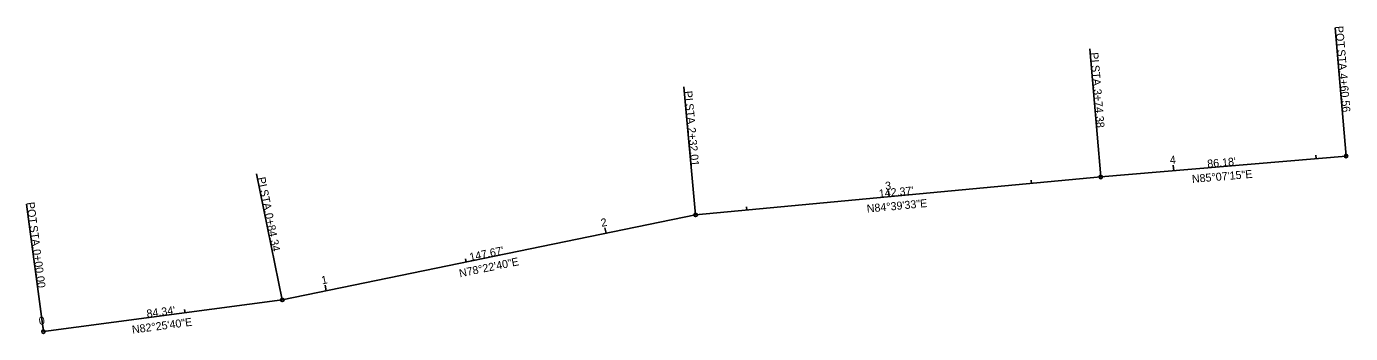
# Model space of a CAD drawing. Extents: x 227242 to 227706, y 293934 to 294041.
import ezdxf

# ---------------------------------------------------------------- set-up
doc = ezdxf.new("R2010")
doc.units = 0
for name, color, linetype in [('GE_P_Alignment', 7, 'Continuous'), ('GE_P_Alignment_100_Bearings', 7, 'Continuous'), ('GE_P_Alignment_100_Cardinal_Points', 7, 'Continuous'), ('GE_P_Alignment_100_Curve_Data', 7, 'Continuous'), ('SC_Scratch1', 7, 'Continuous'), ('SC_Scratch2', 7, 'Continuous')]:
    doc.layers.add(name, color=color, linetype=linetype)

msp = doc.modelspace()

# ---------------------------------------------------------------- linework, layer by layer
at = {"layer": 'GE_P_Alignment'}
for p, q in [((227618.14, 293988.75), (227704.01, 293996.08)), ((227476.38, 293975.49), (227618.14, 293988.75)), ((227331.74, 293945.74), (227476.38, 293975.49)), ((227248.14, 293934.63), (227331.74, 293945.74))]:
    msp.add_line(p, q, dxfattribs=at)
at = {"layer": 'GE_P_Alignment_100_Bearings'}
for p, q in [((227704.01, 293996.08), (227700.18, 294040.91)), ((227618.14, 293988.75), (227614.31, 294033.58)), ((227476.38, 293975.49), (227472.2, 294020.3)), ((227331.74, 293945.74), (227322.68, 293989.82)), ((227248.14, 293934.63), (227242.21, 293979.24))]:
    msp.add_line(p, q, dxfattribs=at)
for centre in [(227704.01, 293996.08), (227618.14, 293988.75), (227476.38, 293975.49), (227331.74, 293945.74), (227248.14, 293934.63)]:
    msp.add_circle(centre, 0.6, dxfattribs=at)
at = {"layer": 'GE_P_Alignment_100_Curve_Data'}
for p, q in [((227693.49, 293995.18), (227693.38, 293996.37)), ((227643.67, 293990.93), (227643.5, 293992.92)), ((227593.87, 293986.48), (227593.75, 293987.67)), ((227544.08, 293981.82), (227543.9, 293983.81)), ((227494.3, 293977.17), (227494.19, 293978.36)), ((227445.03, 293969.05), (227444.63, 293971)), ((227396.06, 293958.97), (227395.82, 293960.15)), ((227347.08, 293948.9), (227346.68, 293950.86)), ((227297.7, 293941.22), (227297.55, 293942.41)), ((227248.14, 293934.63), (227247.88, 293936.61))]:
    msp.add_line(p, q, dxfattribs=at)
at = {"layer": 'SC_Scratch1'}
for p, q in [((227618.14, 293988.75), (227704.01, 293996.08)), ((227476.38, 293975.49), (227618.14, 293988.75)), ((227331.74, 293945.74), (227476.38, 293975.49)), ((227248.14, 293934.63), (227331.74, 293945.74))]:
    msp.add_line(p, q, dxfattribs=at)

# ---------------------------------------------------------------- texts
at = {"layer": 'GE_P_Alignment_100_Bearings'}
for s, rotation, p in [('POT', 274.8792, (227700.18, 294041.49)), ('PI', 274.8792, (227614.47, 294032.24)), (' STA. ', 274.8792, (227700.79, 294034.32)), (' STA. ', 274.8792, (227614.76, 294028.86)), ('4+60.56', 274.8792, (227701.59, 294024.9)), ('PI', 275.3409, (227472.38, 294018.77)), ('3+74.38', 274.8792, (227615.56, 294019.44)), (' STA. ', 275.3409, (227472.7, 294015.4)), ('2+32.01', 275.3409, (227473.58, 294005.99)), ('PI', 281.6223, (227323, 293988.44)), ('POT', 277.5724, (227242.18, 293979.8)), (' STA. ', 281.6223, (227323.69, 293985.12)), ('0+84.34', 281.6223, (227325.59, 293975.86)), (' STA. ', 277.5724, (227243.13, 293972.66)), ('0+00.00', 277.5724, (227244.37, 293963.3))]:
    msp.add_text(s, height=2.8, rotation=rotation, dxfattribs=at).set_placement(p)
at = {"layer": 'GE_P_Alignment_100_Cardinal_Points'}
for s, rotation, p in [("86.18'", 4.8792, (227655.53, 293991.98)), ("142.37'", 5.3409, (227540.61, 293981.54)), ("147.67'", 11.6223, (227397.51, 293959.31)), ("84.34'", 7.5724, (227284.42, 293939.5))]:
    msp.add_text(s, height=2.8, rotation=rotation, dxfattribs=at).set_placement(p)
at = {"layer": 'GE_P_Alignment_100_Curve_Data'}
for s, rotation, p in [('4', 4.8792, (227642.42, 293993.33)), ('3', 5.3409, (227542.82, 293984.22)), ('2', 11.6223, (227443.51, 293971.28)), ('1', 11.6223, (227345.68, 293951.16)), ('0', 7.5724, (227246.71, 293936.96))]:
    msp.add_text(s, height=2.8, rotation=rotation, dxfattribs=at).set_placement(p)
at = {"layer": 'SC_Scratch2'}
for s, rotation, p in [('N85°07\'15"E', 4.8792, (227650.16, 293986.66)), ('N84°39\'33"E', 5.3409, (227536.39, 293976.28)), ('N78°22\'40"E', 11.6223, (227393.9, 293953.63)), ('N82°25\'40"E', 7.5724, (227279.31, 293933.93))]:
    msp.add_text(s, height=2.8, rotation=rotation, dxfattribs=at).set_placement(p)

doc.saveas('drawing.dxf')
